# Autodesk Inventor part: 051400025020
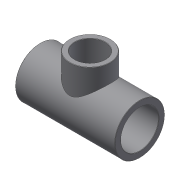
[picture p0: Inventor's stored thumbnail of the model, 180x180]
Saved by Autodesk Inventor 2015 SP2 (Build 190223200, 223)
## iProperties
Created: 2017-10
Part Number: 051400025020
Material: Generic
Description: PLASSON REDUCER TEE - CEMENT PVC 25-20-25
Document SubType Name: Modeling
Designer: KIM
Density: 1 g/cm^3
Appearance: Default
Author: KIM
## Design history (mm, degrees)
derived "051400.ipt"
feature "Solid1::051400.ipt"
feature "Solid2::051400.ipt"
tag "TaggingFeature1"
body "Solid1"
other parameters: "d0" = 66, "d1" = 33, "d2" = 19, "d4" = 25, "d5" = 22.5, "d7" = 0.25, "d8" = 19, "d9" = 28.5, "d10" = 27, "d12" = 18, "d23" = 16, "d24" = 0.25, "d26" = 0, "d30" = 0, "d32" = 0, "d_" = 25, "E_" = 33, "H_" = 66, "l_" = 19, "Z_" = 14, "E_1" = 27, "l_1" = 16, "Z_1" = 12.5, "H_1" = 45
